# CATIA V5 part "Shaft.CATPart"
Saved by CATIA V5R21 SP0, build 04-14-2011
Part number: Shaft
Bounding box of the stored display mesh (mm): x -10.997 to 10.997, y 0 to 134, z -10.875 to 10.875
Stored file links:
  D:\CATIA V5R21 E-RESOURCES\CATIA-V5R21\catia-v5r21-Prts\c14_catia_v5r21_prt\c14-catia-v5r21-figr-14-26 & 27\Part & Asm\Shaft.CATPart
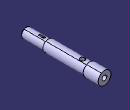
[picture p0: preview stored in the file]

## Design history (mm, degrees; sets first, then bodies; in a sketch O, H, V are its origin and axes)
Body1 (main body)
  Sketch1 on yz-plane, origin (0, 0, 0), H (0, 1, 0), V (0, 0, 1)
    line L1 (0, 0) -> (0, 8)
    line L2 (0, 8) -> (39, 8)
    line L3 (39, 8) -> (39, 9.5)
    line L4 (39, 9.5) -> (109, 9.5)
    line L5 (109, 9.5) -> (109, 11)
    line L6 (109, 11) -> (134, 11)
    line L7 (134, 11) -> (134, 0)
    point P7 (134, 0)
    line L8 (134, 0) -> (0, 0)
    length L1 = 8
    length L8 = 134
    length L7 = 11
    distance L4 L8 = 9.5
    length L6 = 25
    length L4 = 70
    vertical: L1 V, L3 V, L5 V, L7 V
    horizontal: L2 H, L4 H, L6 H, L8 H
    coincidence: P7 H
  Shaft1: profile Sketch1, axis edge of Sketch1, angle 360
  Chamfer1: length 1.5, angle 45, on 1 edge
  Sketch2 on xy-plane, origin (0, 0, 0), H (1, 0, 0), V (0, 1, 0)
    circle A1 centre (0, 97) radius 4.15
    point P1 (0, 97)
    reference projected line E1 (-11, 109) -> (11, 109) from edge of Shaft1
    radius A1 = 4.15
    distance E1 P1 = 12
    coincidence: P1 V
  Pocket1: profile Sketch2, direction (0, 0, -1), length 20, mirrored extent
  Sketch3 on face of Shaft1, origin (0, 134, 0), H (-1, 0, 0), V (0, 0, 1)
    circle A1 centre (0, 0) radius 4.15
    radius A1 = 4.15
  Pocket2: profile Sketch3, direction (0, -1, 0), length 44
  Sketch4 on yz-plane, origin (0, 0, 0), H (0, 1, 0), V (0, 0, 1)
    point P1 (23, 8)
    line L1 (23, 8) -> (33, 8)
    arc A1 centre (28, 12.899) radius 7 from (23, 8) to (33, 8) ccw
    reference projected line E1 (39, -9.5) -> (39, 9.5) from edge of Shaft1
    length L1 = 10
    distance L1 H = 8
    distance P1 E1 = 16
    radius A1 = 7
    horizontal: L1 H
  Pocket3: profile Sketch4, direction (-1, 0, 0), length 1.6, mirrored extent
